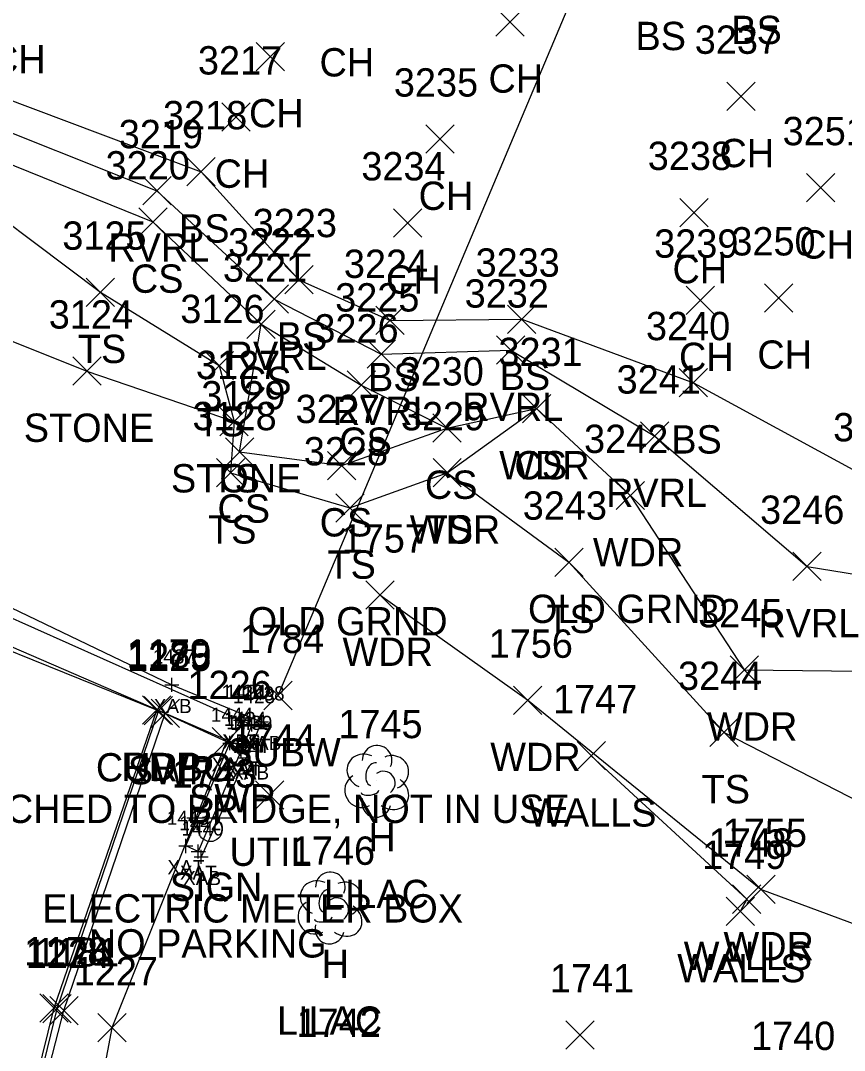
# Model space of a CAD drawing. Extents: x 462930 to 463548, y 29607 to 30453.
# Drawn here: x 463339.03 to 463356.77, y 30103.46 to 30125.62 of the extents above; entities that cross this region are included whole.
import ezdxf

# ---------------------------------------------------------------- set-up
doc = ezdxf.new("R2010")
doc.units = 0
for name, color, linetype in [('B_A', 7, 'Continuous'), ('B_I', 7, 'Continuous'), ('B_TIC', 7, 'Continuous'), ('BSE', 7, 'Continuous'), ('BSUBM', 7, 'Continuous'), ('L_A', 7, 'Continuous'), ('L_C', 7, 'Continuous'), ('L_I', 7, 'Continuous'), ('L_TIC', 7, 'Continuous'), ('LASF', 7, 'Continuous'), ('LAWA', 7, 'Continuous'), ('LAWE', 7, 'Continuous'), ('LELB', 7, 'Continuous'), ('LTD', 7, 'Continuous'), ('LWS', 7, 'Continuous'), ('P_A', 7, 'Continuous'), ('P_I', 7, 'Continuous'), ('P_TIC', 7, 'Continuous'), ('PET', 7, 'Continuous'), ('R_A', 7, 'Continuous'), ('R_I', 7, 'Continuous'), ('R_TIC', 7, 'Continuous'), ('RC', 7, 'Continuous'), ('RSW', 7, 'Continuous'), ('S_A', 7, 'Continuous'), ('S_C', 7, 'Continuous'), ('S_I', 7, 'Continuous'), ('SSGN', 7, 'Continuous'), ('U_A', 7, 'Continuous'), ('U_C', 7, 'Continuous'), ('U_I', 7, 'Continuous'), ('U_TIC', 7, 'Continuous'), ('UDEFAULT', 7, 'Continuous'), ('UW', 7, 'Continuous')]:
    doc.layers.add(name, color=color, linetype=linetype)

msp = doc.modelspace()

# ---------------------------------------------------------------- linework, layer by layer
at = {"layer": 'B_TIC'}
for p, q in [((463342.288, 30111.327), (463342.311, 30111.327)), ((463343.765, 30110.564), (463343.788, 30110.564)), ((463343.765, 30110.564), (463343.788, 30110.564)), ((463343.766, 30110.566), (463343.789, 30110.566)), ((463344.217, 30110.532), (463344.24, 30110.532)), ((463344.012, 30110.471), (463344.035, 30110.471)), ((463343.537, 30110.073), (463343.56, 30110.073)), ((463343.779, 30109.913), (463343.802, 30109.913)), ((463343.82, 30109.984), (463343.843, 30109.984)), ((463343.955, 30109.898), (463343.978, 30109.898)), ((463342.588, 30107.859), (463342.611, 30107.859)), ((463342.856, 30107.741), (463342.879, 30107.741)), ((463342.92, 30107.626), (463342.943, 30107.626))]:
    msp.add_line(p, q, dxfattribs=at)
for points in [[(463342.287, 30111.175), (463342.287, 30111.479)], [(463342.135, 30111.327), (463342.439, 30111.327)], [(463343.764, 30110.412), (463343.764, 30110.716)], [(463343.764, 30110.412), (463343.764, 30110.716)], [(463343.765, 30110.414), (463343.765, 30110.718)], [(463343.612, 30110.564), (463343.916, 30110.564)], [(463343.612, 30110.564), (463343.916, 30110.564)], [(463343.613, 30110.566), (463343.917, 30110.566)], [(463344.011, 30110.319), (463344.011, 30110.623)], [(463344.064, 30110.532), (463344.368, 30110.532)], [(463344.216, 30110.38), (463344.216, 30110.684)], [(463343.859, 30110.471), (463344.163, 30110.471)], [(463343.384, 30110.073), (463343.688, 30110.073)], [(463343.536, 30109.921), (463343.536, 30110.225)], [(463343.778, 30109.761), (463343.778, 30110.065)], [(463343.819, 30109.832), (463343.819, 30110.136)], [(463343.954, 30109.746), (463343.954, 30110.05)], [(463343.626, 30109.913), (463343.93, 30109.913)], [(463343.667, 30109.984), (463343.971, 30109.984)], [(463343.802, 30109.898), (463344.106, 30109.898)], [(463342.435, 30107.859), (463342.739, 30107.859)], [(463342.587, 30107.707), (463342.587, 30108.011)], [(463342.855, 30107.589), (463342.855, 30107.893)], [(463342.703, 30107.741), (463343.007, 30107.741)], [(463342.767, 30107.626), (463343.071, 30107.626)], [(463342.919, 30107.474), (463342.919, 30107.778)]]:
    msp.add_lwpolyline(points, dxfattribs=at)
at = {"layer": 'BSE'}
for points in [[(463333.405, 30115.185), (463343.765, 30110.566)], [(463343.765, 30110.566), (463343.764, 30110.564)]]:
    msp.add_lwpolyline(points, dxfattribs=at)
at = {"layer": 'BSUBM'}
for points in [[(463331.088, 30115.549), (463331.347, 30116.049), (463332.9, 30115.442), (463333.896, 30115.351), (463342.287, 30111.327), (463344.216, 30110.532), (463343.954, 30109.898), (463342.919, 30107.626)], [(463343.764, 30110.564), (463344.011, 30110.471), (463343.819, 30109.984), (463332.88, 30114.719), (463333.067, 30115.223), (463333.395, 30115.186)], [(463343.778, 30109.913), (463342.855, 30107.741), (463342.587, 30107.859), (463343.536, 30110.073)], [(463343.536, 30110.073), (463343.778, 30109.913)]]:
    msp.add_lwpolyline(points, dxfattribs=at)
at = {"layer": 'L_TIC'}
for points in [[(463349.259, 30125.286), (463349.869, 30125.895)], [(463349.869, 30125.286), (463349.259, 30125.895)], [(463344.104, 30124.54), (463344.714, 30125.15)], [(463344.714, 30124.54), (463344.104, 30125.15)], [(463354.233, 30123.683), (463354.843, 30124.293)], [(463354.843, 30123.683), (463354.233, 30124.293)], [(463343.362, 30123.239), (463343.972, 30123.849)], [(463343.972, 30123.239), (463343.362, 30123.849)], [(463347.755, 30122.764), (463348.365, 30123.373)], [(463348.365, 30122.764), (463347.755, 30123.373)], [(463342.611, 30122.06), (463343.221, 30122.669)], [(463343.221, 30122.06), (463342.611, 30122.669)], [(463341.661, 30121.653), (463342.271, 30122.262)], [(463342.271, 30121.653), (463341.661, 30122.262)], [(463355.952, 30121.717), (463356.562, 30122.326)], [(463356.562, 30121.717), (463355.952, 30122.326)], [(463353.221, 30121.183), (463353.83, 30121.793)], [(463353.83, 30121.183), (463353.221, 30121.793)], [(463341.574, 30120.98), (463342.183, 30121.59)], [(463342.183, 30120.98), (463341.574, 30121.59)], [(463347.055, 30120.96), (463347.665, 30121.569)], [(463347.665, 30120.96), (463347.055, 30121.569)], [(463344.716, 30119.739), (463345.326, 30120.348)], [(463345.326, 30119.739), (463344.716, 30120.348)], [(463340.443, 30119.468), (463341.052, 30120.078)], [(463341.052, 30119.468), (463340.443, 30120.078)], [(463344.186, 30119.321), (463344.795, 30119.93)], [(463344.795, 30119.321), (463344.186, 30119.93)], [(463353.361, 30119.297), (463353.97, 30119.907)], [(463353.97, 30119.297), (463353.361, 30119.907)], [(463355.048, 30119.345), (463355.658, 30119.955)], [(463355.658, 30119.345), (463355.048, 30119.955)], [(463343.901, 30118.781), (463344.511, 30119.39)], [(463344.511, 30118.781), (463343.901, 30119.39)], [(463343.901, 30118.781), (463344.511, 30119.39)], [(463344.511, 30118.781), (463343.901, 30119.39)], [(463346.679, 30118.862), (463347.289, 30119.472)], [(463347.289, 30118.862), (463346.679, 30119.472)], [(463349.514, 30118.888), (463350.124, 30119.497)], [(463350.124, 30118.888), (463349.514, 30119.497)], [(463346.491, 30118.139), (463347.1, 30118.749)], [(463347.1, 30118.139), (463346.491, 30118.749)], [(463349.279, 30118.223), (463349.889, 30118.832)], [(463349.889, 30118.223), (463349.279, 30118.832)], [(463343.001, 30117.89), (463343.61, 30118.5)], [(463343.61, 30117.89), (463343.001, 30118.5)], [(463340.152, 30117.772), (463340.762, 30118.382)], [(463340.762, 30117.772), (463340.152, 30118.382)], [(463346.059, 30117.472), (463346.669, 30118.081)], [(463346.669, 30117.472), (463346.059, 30118.081)], [(463353.209, 30117.521), (463353.819, 30118.131)], [(463353.819, 30117.521), (463353.209, 30118.131)], [(463349.833, 30116.965), (463350.442, 30117.575)], [(463350.442, 30116.965), (463349.833, 30117.575)], [(463349.833, 30116.965), (463350.442, 30117.575)], [(463350.442, 30116.965), (463349.833, 30117.575)], [(463343.32, 30116.684), (463343.93, 30117.294)], [(463343.93, 30116.684), (463343.32, 30117.294)], [(463343.32, 30116.684), (463343.93, 30117.294)], [(463343.93, 30116.684), (463343.32, 30117.294)], [(463343.32, 30116.684), (463343.93, 30117.294)], [(463343.93, 30116.684), (463343.32, 30117.294)], [(463347.904, 30116.546), (463348.514, 30117.156)], [(463348.514, 30116.546), (463347.904, 30117.156)], [(463347.904, 30116.546), (463348.514, 30117.156)], [(463348.514, 30116.546), (463347.904, 30117.156)], [(463352.377, 30116.373), (463352.986, 30116.982)], [(463352.986, 30116.373), (463352.377, 30116.982)], [(463343.439, 30116.033), (463344.048, 30116.643)], [(463344.048, 30116.033), (463343.439, 30116.643)], [(463343.439, 30116.033), (463344.048, 30116.643)], [(463344.048, 30116.033), (463343.439, 30116.643)], [(463345.639, 30115.738), (463346.249, 30116.347)], [(463346.249, 30115.738), (463345.639, 30116.347)], [(463343.246, 30115.584), (463343.856, 30116.194)], [(463343.856, 30115.584), (463343.246, 30116.194)], [(463347.909, 30115.583), (463348.518, 30116.193)], [(463348.518, 30115.583), (463347.909, 30116.193)], [(463347.909, 30115.583), (463348.518, 30116.193)], [(463348.518, 30115.583), (463347.909, 30116.193)], [(463351.85, 30115.095), (463352.459, 30115.704)], [(463352.459, 30115.095), (463351.85, 30115.704)], [(463345.816, 30114.828), (463346.426, 30115.437)], [(463346.426, 30114.828), (463345.816, 30115.437)], [(463350.53, 30113.66), (463351.14, 30114.269)], [(463351.14, 30113.66), (463350.53, 30114.269)], [(463355.656, 30113.57), (463356.266, 30114.18)], [(463356.266, 30113.57), (463355.656, 30114.18)], [(463346.459, 30112.952), (463347.069, 30113.562)], [(463347.069, 30112.952), (463346.459, 30113.562)], [(463354.307, 30111.343), (463354.916, 30111.952)], [(463354.916, 30111.343), (463354.307, 30111.952)], [(463349.64, 30110.688), (463350.25, 30111.298)], [(463350.25, 30110.688), (463349.64, 30111.298)], [(463353.872, 30109.996), (463354.482, 30110.606)], [(463354.482, 30109.996), (463353.872, 30110.606)], [(463351.009, 30109.495), (463351.619, 30110.105)], [(463351.619, 30109.495), (463351.009, 30110.105)], [(463354.662, 30106.618), (463355.272, 30107.228)], [(463355.272, 30106.618), (463354.662, 30107.228)], [(463354.36, 30106.409), (463354.97, 30107.019)], [(463354.97, 30106.409), (463354.36, 30107.019)], [(463354.219, 30106.145), (463354.829, 30106.755)], [(463354.829, 30106.145), (463354.219, 30106.755)], [(463350.768, 30103.487), (463351.378, 30104.097)], [(463351.378, 30103.487), (463350.768, 30104.097)]]:
    msp.add_lwpolyline(points, dxfattribs=at)
at = {"layer": 'LASF'}
msp.add_lwpolyline([(463302.508, 30136.744), (463309.807, 30134.07), (463314.097, 30132.787), (463314.835, 30129.355), (463318.543, 30127.958), (463323.464, 30127.612), (463327.985, 30126.286), (463331.81, 30124.74), (463337.174, 30122.457), (463335.599, 30120.018), (463340.457, 30118.077), (463343.625, 30116.989)], dxfattribs=at)
at = {"layer": 'LAWA'}
for points in [[(463348.213, 30115.888), (463350.137, 30117.27), (463352.155, 30115.4), (463354.611, 30111.648), (463359.628, 30111.593), (463364.564, 30109.359), (463367.92, 30105.253), (463371.613, 30104.325)], [(463376.21, 30084.746), (463374.716, 30092.638), (463372.085, 30098.596), (463365.52, 30103.015), (463354.967, 30106.923), (463349.945, 30110.993), (463346.764, 30113.257)]]:
    msp.add_lwpolyline(points, dxfattribs=at)
at = {"layer": 'LAWE'}
msp.add_lwpolyline([(463303.761, 30138.951), (463311.513, 30136.497), (463315.004, 30134.116), (463316.958, 30131.951), (463319.339, 30130.596), (463324.938, 30129.932), (463327.547, 30128.313), (463332.975, 30126.47), (463337.641, 30123.674), (463341.966, 30121.958), (463344.49, 30119.626), (463346.795, 30118.444), (463349.584, 30118.528), (463352.681, 30116.677), (463355.961, 30113.875), (463359.993, 30113.221), (463365.135, 30110.482), (463368.778, 30108.638), (463372.593, 30105.432)], dxfattribs=at)
at = {"layer": 'LELB'}
for points in [[(463303.951, 30140.018), (463311.358, 30137.763), (463317.49, 30134.193), (463325.042, 30130.081), (463328.062, 30128.844), (463333.248, 30127.486), (463337.89, 30124.253), (463342.916, 30122.365), (463345.021, 30120.043), (463346.984, 30119.167), (463349.819, 30119.192), (463353.514, 30117.826), (463357.518, 30115.65), (463360.726, 30114.785), (463365.845, 30111.76), (463369.152, 30109.504), (463372.544, 30107.449)], [(463303.076, 30138.323), (463311.018, 30135.245), (463314.543, 30133.39), (463316.477, 30129.737), (463318.725, 30129.305), (463323.995, 30128.426), (463327.48, 30127.705), (463332.775, 30125.956), (463337.384, 30123.1), (463341.878, 30121.285), (463344.206, 30119.085), (463346.364, 30117.777), (463348.209, 30116.851), (463350.137, 30117.27)], [(463337.174, 30122.457), (463340.747, 30119.773), (463343.306, 30118.195), (463343.625, 30116.989)], [(463343.743, 30116.338), (463344.206, 30119.085)], [(463343.625, 30116.989), (463343.551, 30115.889), (463346.121, 30115.132), (463348.213, 30115.888), (463350.835, 30113.965), (463354.177, 30110.301), (463358.469, 30108.098), (463361.951, 30106.722), (463364.431, 30105.371), (463367.498, 30103.77), (463369.557, 30101.829)], [(463343.743, 30116.338), (463345.944, 30116.042), (463348.209, 30116.851)]]:
    msp.add_lwpolyline(points, dxfattribs=at)
at = {"layer": 'LTD'}
for p, q in [((463346.691, 30109.264), (463346.691, 30109.264)), ((463346.691, 30109.264), (463346.691, 30109.264)), ((463345.685, 30106.539), (463345.685, 30106.539)), ((463345.685, 30106.539), (463345.685, 30106.539))]:
    msp.add_line(p, q, dxfattribs=at)
for centre in [(463346.705, 30109.701), (463345.699, 30106.976)]:
    msp.add_arc(centre, 0.319, 335.5272, 180.9563, dxfattribs=at)
for centre, major_axis, ratio, start_param, end_param in [((463346.45, 30109.467), (0.369, -0.156), 0.895232, 1.570796, 4.712389), ((463347.008, 30109.442), (-0.348, -0.147), 0.949671, 1.570796, 4.712389), ((463346.627, 30109.404), (-0.063, -0.241), 0.645439, 3.141593, 6.283185), ((463346.843, 30109.213), (-0.152, 0.203), 0.989748, 3.141593, 6.283185), ((463346.361, 30109.048), (0.178, -0.317), 0.959034, 3.141593, 6.283185), ((463346.996, 30109.01), (-0.332, 0.241), 0.841452, 1.570796, 4.712389), ((463346.551, 30109.035), (-0.19, -0.025), 0.423636, 0, 3.141593), ((463346.691, 30108.807), (0.081, 0.323), 0.942809, 1.570796, 4.712389), ((463345.444, 30106.742), (0.369, -0.156), 0.895232, 1.570796, 4.712389), ((463345.621, 30106.679), (-0.063, -0.241), 0.645439, 3.141593, 6.283185), ((463346.002, 30106.717), (-0.348, -0.147), 0.949671, 1.570796, 4.712389), ((463345.837, 30106.488), (-0.152, 0.203), 0.989748, 3.141593, 6.283185), ((463345.355, 30106.323), (0.178, -0.317), 0.959034, 3.141593, 6.283185), ((463345.99, 30106.285), (-0.332, 0.241), 0.841452, 1.570796, 4.712389), ((463345.545, 30106.31), (-0.19, -0.025), 0.423636, 0, 3.141593), ((463345.685, 30106.082), (0.081, 0.323), 0.942809, 1.570796, 4.712389)]:
    msp.add_ellipse(centre, major_axis=major_axis, ratio=ratio, start_param=start_param, end_param=end_param, dxfattribs=at)
at = {"layer": 'LWS'}
msp.add_lwpolyline([(463351.314, 30109.8), (463354.665, 30106.714), (463354.524, 30106.45)], dxfattribs=at)
at = {"layer": 'P_TIC'}
for points in [[(463341.656, 30110.478), (463342.266, 30111.088)], [(463342.266, 30110.478), (463341.656, 30111.088)], [(463339.446, 30104.069), (463340.056, 30104.679)], [(463340.056, 30104.069), (463339.446, 30104.679)]]:
    msp.add_lwpolyline(points, dxfattribs=at)
at = {"layer": 'PET'}
for points in [[(463341.961, 30110.783), (463337.978, 30112.385)], [(463374.338, 29956.391), (463367.555, 29969.533), (463365.556, 29974.625), (463364.583, 29976.896), (463356.695, 29995.475), (463352.505, 30009.098), (463350.167, 30017.966), (463347.98, 30027.115), (463347.733, 30028.32), (463346.051, 30037.294), (463343.907, 30048.483), (463342.761, 30054.643), (463342.551, 30055.85), (463341.301, 30062.483), (463338.432, 30077.399), (463338.227, 30078.623), (463337.48, 30086.968), (463337.479, 30088.196), (463338.474, 30099.226), (463339.751, 30104.374), (463341.961, 30110.783)]]:
    msp.add_lwpolyline(points, dxfattribs=at)
at = {"layer": 'R_TIC'}
for points in [[(463341.691, 30110.465), (463342.301, 30111.075)], [(463342.301, 30110.465), (463341.691, 30111.075)], [(463341.837, 30110.404), (463342.447, 30111.014)], [(463342.447, 30110.404), (463341.837, 30111.014)], [(463343.155, 30109.8), (463343.765, 30110.41)], [(463343.765, 30109.8), (463343.155, 30110.41)], [(463339.506, 30104.05), (463340.116, 30104.66)], [(463340.116, 30104.05), (463339.506, 30104.66)], [(463339.656, 30104.013), (463340.266, 30104.623)], [(463340.266, 30104.013), (463339.656, 30104.623)], [(463340.689, 30103.641), (463341.299, 30104.251)], [(463341.299, 30103.641), (463340.689, 30104.251)]]:
    msp.add_lwpolyline(points, dxfattribs=at)
at = {"layer": 'RC'}
for points in [[(463341.996, 30110.77), (463339.811, 30104.355), (463338.55, 30099.207), (463337.573, 30088.196), (463337.545, 30086.968)], [(463341.996, 30110.77), (463342.142, 30110.709)]]:
    msp.add_lwpolyline(points, dxfattribs=at)
at = {"layer": 'RSW'}
msp.add_lwpolyline([(463338.63, 30099.17), (463339.961, 30104.318), (463342.142, 30110.709), (463343.46, 30110.105), (463340.994, 30103.946), (463340.038, 30098.879)], dxfattribs=at)
at = {"layer": 'SSGN'}
for p, q in [((463342.612, 30108.461), (463343.628, 30108.461)), ((463343.114, 30108.207), (463343.114, 30108.207))]:
    msp.add_line(p, q, dxfattribs=at)
msp.add_circle((463343.114, 30108.207), 0.254, dxfattribs=at)
at = {"layer": 'U_TIC'}
for points in [[(463344.268, 30110.791), (463344.878, 30111.401)], [(463344.878, 30110.791), (463344.268, 30111.401)]]:
    msp.add_lwpolyline(points, dxfattribs=at)
at = {"layer": 'UDEFAULT'}
for points in [[(463344.087, 30108.649), (463344.697, 30109.259)], [(463344.697, 30108.649), (463344.087, 30109.259)]]:
    msp.add_lwpolyline(points, dxfattribs=at)
at = {"layer": 'UW'}
msp.add_lwpolyline([(463344.573, 30111.096), (463359.121, 30145.596)], dxfattribs=at)

# ---------------------------------------------------------------- texts
at = {"layer": 'B_A'}
for s, p in [('XAB', (463341.897, 30110.717)), ('XBS', (463343.38, 30109.954)), ('XBS', (463343.381, 30109.956)), ('XAT', (463343.369, 30109.954)), ('XAT', (463343.616, 30109.861)), ('XAB', (463343.826, 30109.922)), ('XAT', (463343.141, 30109.463)), ('XAT', (463343.383, 30109.303)), ('XAT', (463343.424, 30109.374)), ('XAB', (463343.564, 30109.288)), ('XAT', (463342.192, 30107.249)), ('XAT', (463342.46, 30107.131)), ('XAB', (463342.529, 30107.016))]:
    msp.add_text(s, height=0.3048, dxfattribs=at).set_placement(p)
at = {"layer": 'B_I'}
for s, p in [('1437', (463341.877, 30111.784)), ('1422', (463343.354, 30111.021)), ('1422', (463343.354, 30111.021)), ('1421', (463343.441, 30111.023)), ('1423', (463343.601, 30110.928)), ('1438', (463343.806, 30110.989)), ('1444', (463343.126, 30110.53)), ('1424', (463343.409, 30110.441)), ('1441', (463343.454, 30110.37)), ('1439', (463343.542, 30110.355)), ('1443', (463342.177, 30108.316)), ('1442', (463342.445, 30108.198)), ('1440', (463342.495, 30108.083))]:
    msp.add_text(s, height=0.3048, dxfattribs=at).set_placement(p)
at = {"layer": 'L_A'}
for s, height, p in [('BS', 0.6096, (463352.268, 30124.982)), ('BS', 0.6096, (463354.331, 30125.112)), ('CH', 0.6096, (463338.392, 30124.48)), ('CH', 0.6096, (463345.465, 30124.416)), ('CH', 0.6096, (463349.103, 30124.066)), ('CH', 0.6096, (463343.948, 30123.321)), ('CH', 0.6096, (463354.077, 30122.464)), ('CH', 0.6096, (463343.206, 30122.02)), ('CH', 0.6096, (463347.599, 30121.544)), ('BS', 0.6096, (463342.441, 30120.841)), ('RVRL', 0.6096, (463340.919, 30120.434)), ('CH', 0.6096, (463355.796, 30120.497)), ('CH', 0.6096, (463353.065, 30119.964)), ('CS', 0.6096, (463341.403, 30119.761)), ('CH', 0.6096, (463346.899, 30119.74)), ('BS', 0.6096, (463344.546, 30118.519)), ('TS', 0.6096, (463340.263, 30118.249)), ('RVRL', 0.6096, (463343.444, 30118.102)), ('CH', 0.6096, (463353.205, 30118.078)), ('CH', 0.6096, (463354.892, 30118.126)), ('BS', 0.6096, (463346.509, 30117.643)), ('BS', 0.6096, (463349.344, 30117.668)), ('CS', 0.6096, (463343.731, 30117.561)), ('CS', 0.6096, (463343.731, 30117.561)), ('RVRL', 0.6096, (463348.537, 30117.004)), ('RVRL', 0.6096, (463345.749, 30116.92)), ('STONE', 0.6096, (463339.098, 30116.553)), ('TS', 0.6096, (463342.821, 30116.671)), ('BS', 0.6096, (463353.039, 30116.302)), ('CS', 0.6096, (463345.889, 30116.253)), ('WDR', 0.6096, (463349.334, 30115.746)), ('CS', 0.6096, (463349.662, 30115.746)), ('STONE', 0.6096, (463342.267, 30115.465)), ('TS', 0.6096, (463343.14, 30115.465)), ('TS', 0.6096, (463343.14, 30115.465)), ('CS', 0.6096, (463347.734, 30115.327)), ('CS', 0.6096, (463347.734, 30115.327)), ('RVRL', 0.6096, (463351.635, 30115.153)), ('CS', 0.6096, (463343.268, 30114.814)), ('CS', 0.6096, (463343.268, 30114.814)), ('TS', 0.6096, (463343.066, 30114.365)), ('CS', 0.6096, (463345.469, 30114.518)), ('WDR', 0.6096, (463347.409, 30114.364)), ('TS', 0.6096, (463347.729, 30114.364)), ('WDR', 0.6096, (463351.351, 30113.876)), ('TS', 0.6096, (463345.636, 30113.608)), ('TS', 0.6096, (463350.35, 30112.441)), ('RVRL', 0.6096, (463354.915, 30112.351)), ('WDR', 0.6096, (463345.96, 30111.733)), ('WDR', 0.6096, (463353.807, 30110.124)), ('WDR', 0.6096, (463349.141, 30109.469)), ('TS', 0.6096, (463353.692, 30108.777)), ('WALLS', 0.6096, (463349.956, 30108.276)), ('H', 0.61, (463346.518, 30107.74)), ('WDR', 0.6096, (463354.163, 30105.399)), ('H', 0.61, (463345.512, 30105.015)), ('WALLS', 0.6096, (463353.307, 30105.19)), ('WALLS', 0.6096, (463353.166, 30104.926))]:
    msp.add_text(s, height=height, dxfattribs=at).set_placement(p)
at = {"layer": 'L_C'}
for s, p in [('OLD GRND', (463349.954, 30112.656)), ('OLD GRND', (463343.92, 30112.389)), ('LILAC', (463345.556, 30106.521)), ('LILAC', (463344.55, 30103.796))]:
    msp.add_text(s, height=0.6096, dxfattribs=at).set_placement(p)
at = {"layer": 'L_I'}
for s, p in [('3237', (463353.544, 30124.903)), ('3217', (463342.847, 30124.458)), ('3235', (463347.066, 30123.983)), ('3218', (463342.095, 30123.279)), ('3219', (463341.143, 30122.872)), ('3251', (463355.436, 30122.936)), ('3238', (463352.532, 30122.403)), ('3220', (463340.859, 30122.199)), ('3234', (463346.366, 30122.179)), ('3223', (463344.027, 30120.958)), ('3125', (463339.927, 30120.687)), ('3222', (463343.497, 30120.54)), ('3239', (463352.67, 30120.516)), ('3250', (463354.333, 30120.564)), ('3224', (463345.99, 30120.081)), ('3233', (463348.825, 30120.107)), ('3221', (463343.385, 30120)), ('3221', (463343.385, 30120)), ('3232', (463348.59, 30119.442)), ('3225', (463345.802, 30119.358)), ('3124', (463339.636, 30118.991)), ('3126', (463342.468, 30119.109)), ('3240', (463352.494, 30118.741)), ('3226', (463345.354, 30118.691)), ('3231', (463349.317, 30118.184)), ('3231', (463349.317, 30118.184)), ('3127', (463342.804, 30117.904)), ('3127', (463342.804, 30117.904)), ('3127', (463342.804, 30117.904)), ('3230', (463347.189, 30117.766)), ('3230', (463347.189, 30117.766)), ('3241', (463351.861, 30117.592)), ('3129', (463342.92, 30117.252)), ('3129', (463342.92, 30117.252)), ('3128', (463342.73, 30116.804)), ('3227', (463344.95, 30116.957)), ('3229', (463347.217, 30116.802)), ('3229', (463347.217, 30116.802)), ('3247', (463356.524, 30116.564)), ('3247', (463356.524, 30116.564)), ('3242', (463351.161, 30116.314)), ('3228', (463345.127, 30116.047)), ('3243', (463349.841, 30114.879)), ('3246', (463354.951, 30114.789)), ('1757', (463345.943, 30114.171)), ('3245', (463353.618, 30112.562)), ('1756', (463349.107, 30111.907)), ('3244', (463353.184, 30111.215)), ('1747', (463350.493, 30110.714)), ('1745', (463345.87, 30110.178)), ('1755', (463354.146, 30107.837)), ('1746', (463344.847, 30107.453)), ('1748', (463353.844, 30107.628)), ('1749', (463353.701, 30107.364)), ('1741', (463350.425, 30104.706)), ('1742', (463344.972, 30103.751)), ('1740', (463354.757, 30103.468))]:
    msp.add_text(s, height=0.6096, dxfattribs=at).set_placement(p)
at = {"layer": 'P_A'}
msp.add_text('RDP', height=0.6096, dxfattribs=at).set_placement((463341.195, 30109.259))
at = {"layer": 'P_I'}
for s, p in [('1179', (463341.311, 30111.697)), ('1178', (463339.103, 30105.288))]:
    msp.add_text(s, height=0.6096, dxfattribs=at).set_placement(p)
at = {"layer": 'R_A'}
for s, p in [('CURBG', (463340.65, 30109.246)), ('SWP', (463341.338, 30109.185)), ('SWP', (463342.656, 30108.581))]:
    msp.add_text(s, height=0.6096, dxfattribs=at).set_placement(p)
at = {"layer": 'R_I'}
for s, p in [('1180', (463341.322, 30111.684)), ('1225', (463341.321, 30111.623)), ('1226', (463342.622, 30111.019)), ('1224', (463339.14, 30105.232)), ('1181', (463339.336, 30105.269)), ('1227', (463340.173, 30104.86))]:
    msp.add_text(s, height=0.6096, dxfattribs=at).set_placement(p)
at = {"layer": 'S_A'}
msp.add_text('SIGN', height=0.6096, dxfattribs=at).set_placement((463342.242, 30106.677))
at = {"layer": 'S_C'}
msp.add_text('NO PARKING', height=0.6096, dxfattribs=at).set_placement((463340.499, 30105.458))
at = {"layer": 'S_I'}
msp.add_text('1743', height=0.6096, dxfattribs=at).set_placement((463342.287, 30109.115))
at = {"layer": 'U_A'}
for s, p in [('SUBW', (463343.479, 30109.572)), ('UTIL', (463343.528, 30107.43))]:
    msp.add_text(s, height=0.6096, dxfattribs=at).set_placement(p)
at = {"layer": 'U_C'}
for s, p in [('ATTACHED TO BRIDGE, NOT IN USE', (463336.629, 30108.353)), ('ELECTRIC METER BOX', (463339.496, 30106.211))]:
    msp.add_text(s, height=0.6096, dxfattribs=at).set_placement(p)
at = {"layer": 'U_I'}
for s, p in [('1784', (463343.752, 30112.01)), ('1744', (463343.571, 30109.868))]:
    msp.add_text(s, height=0.6096, dxfattribs=at).set_placement(p)

doc.saveas('drawing.dxf')
